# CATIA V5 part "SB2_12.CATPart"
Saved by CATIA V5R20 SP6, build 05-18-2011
Part number: SB2_12
Material "Green Blue": density 7860 kg/m3, Young's modulus 2e+11 Pa, Poisson ratio 0.266
Bounding box of the stored display mesh (mm): x 0 to 158, y 0 to 948, z 0 to 49.2
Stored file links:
  E:\#01 CATIA Lecture Materials\#06 DMU\#11 DMU Page01 KIN EX11\SB2_12.CATPart
  C:\Program Files\Dassault Systemes\B20\win_b64\startup\materials\Catalog.CATMaterial
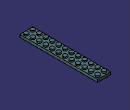
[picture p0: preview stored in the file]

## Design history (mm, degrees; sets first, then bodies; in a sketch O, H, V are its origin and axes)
Body1 (main body), material "Green Blue"
  Sketch1 on xy-plane, origin (0, 0, 0), H (1, 0, 0), V (0, 1, 0)
    circle A1 centre (39.5, 39.5) radius 24.5
    point P1 (39.5, 39.5)
    radius A1 = 24.5
    distance P1 H = 39.5
    distance P1 V = 39.5
  Pad1: profile Sketch1, direction (0, 0, 1), length 49.2
  Sketch2 on xy-plane, origin (0, 0, 0), H (1, 0, 0), V (0, 1, 0)
    point P1 (0, 948)
    line L1 (0, 948) -> (158, 948)
    line L2 (158, 948) -> (158, 0)
    line L3 (158, 0) -> (0, 0)
    line L4 (0, 0) -> (0, 948)
    point P3 (158, 0)
    distance L2 L4 = 158
    distance L1 L3 = 948 {= RectPattern2.Nb1  * 79mm}
    coincidence: P1 V, P3 H
    horizontal: L1 H, L3 H
    vertical: L2 V, L4 V
  Pad2: profile Sketch2, direction (0, 0, 1), length 32
  RectPattern1: of Pad1, direction 1 instances 2, spacing 79, along edge [face of Pad2 from Sketch2.L3 | end face of Pad2]
  RectPattern2: of RectPattern1, direction 1 instances 12, spacing 79, along edge [face of Pad2 from Sketch2.L2 | end face of Pad2]
  Shell1: ExtOffset 0, Face face of Pad2, IntOffset 15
